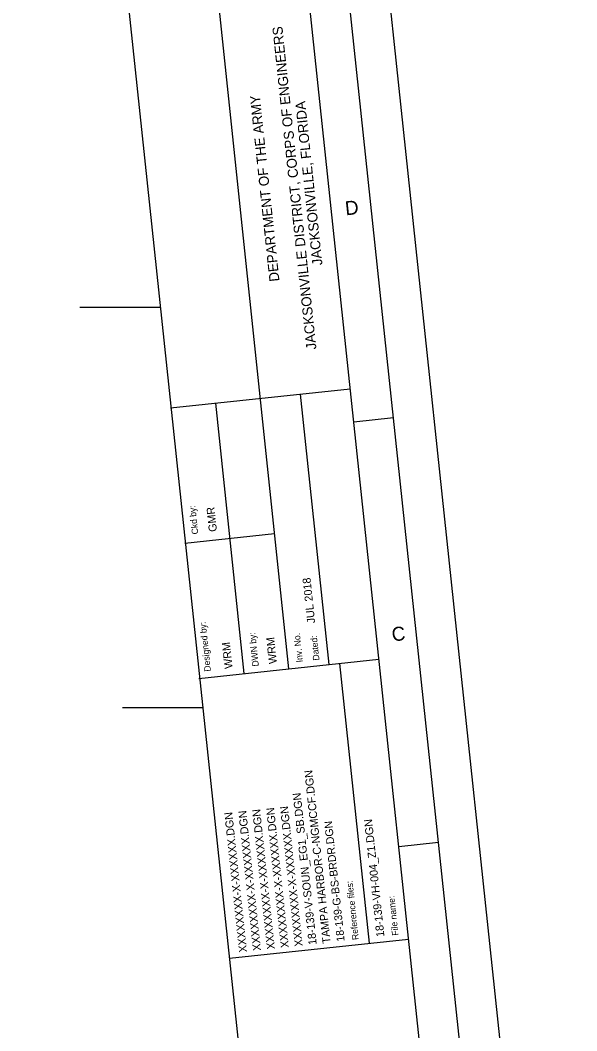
# Model space of a CAD drawing. Extents: x 341472 to 346206, y 1184213 to 1188058.
# Drawn here: x 345511 to 346206, y 1185596 to 1186858 of the extents above; entities that cross this region are included whole.
import ezdxf

# ---------------------------------------------------------------- set-up
doc = ezdxf.new("R2010")
doc.units = 0
for name, color, linetype in [('G-ANNO-NPLT', 7, 'Continuous'), ('G-ANNO-TEXT-DRWG', 7, 'Continuous'), ('G-ANNO-TEXT-PROJ', 7, 'Continuous'), ('G-ANNO-TEXT-TTLB', 7, 'Continuous'), ('G-ANNO-TTLB', 7, 'Continuous'), ('V-TOPO-COOR-STAT', 7, 'Continuous')]:
    doc.layers.add(name, color=color, linetype=linetype)

msp = doc.modelspace()

# ---------------------------------------------------------------- linework, layer by layer
at = {"layer": 'G-ANNO-NPLT'}
msp.add_lwpolyline([(341472, 1187593.7), (345847.5, 1188057.5), (346205.9, 1184676.5), (341830.4, 1184212.7)], close=True, dxfattribs=at)
at = {"layer": 'G-ANNO-TTLB'}
for p, q in [((345534.8, 1187923.8), (345872.1, 1184741.6)), ((345846.1, 1186048.3), (345756.1, 1186903.2)), ((345698.3, 1186374.2), (345922.8, 1186398)), ((345860.2, 1186391.4), (345896, 1186053.6)), ((345790.4, 1186042.5), (345754.9, 1186380.2)), ((345977, 1186361.6), (345927.2, 1186356.3)), ((345716.2, 1186205.3), (345828.3, 1186217.2)), ((345733.7, 1186036.4), (345958.6, 1186060.3)), ((345909.6, 1186055.1), (345946.6, 1185705.6)), ((346033.2, 1185831.3), (345983.4, 1185826)), ((345771.9, 1185687.1), (345995.7, 1185710.8))]:
    msp.add_line(p, q, dxfattribs=at)
for points in [[(341874.8, 1184267.7), (346150.9, 1184720.9), (345803, 1188002.5), (341527, 1187549.3)], [(345758.6, 1187947.5), (341656.6, 1187512.7), (341993.9, 1184330.6), (346095.9, 1184765.4)]]:
    msp.add_lwpolyline(points, close=True, dxfattribs=at)
at = {"layer": 'V-TOPO-COOR-STAT'}
for p, q in [((345585.2, 1186500), (345685.7, 1186500)), ((345638.2, 1186000), (345738.7, 1186000))]:
    msp.add_line(p, q, dxfattribs=at)

# ---------------------------------------------------------------- texts
at = {"layer": 'G-ANNO-TEXT-DRWG'}
for s, p in [('GMR', (345756.4, 1186220)), ('WRM', (345776, 1186049)), ('WRM', (345831.3, 1186055.1)), ('TAMPA HARBOR-C-NGMCCF.DGN', (345898.4, 1185705.9)), ('18-139-V-SOUN_EG1_SB.DGN', (345881, 1185704.1)), ('XXXXXXXX-X-XXXXXX.DGN', (345863.6, 1185702.2)), ('XXXXXXXX-X-XXXXXX.DGN', (345794, 1185694.8)), ('XXXXXXXX-X-XXXXXX.DGN', (345811.4, 1185696.7)), ('XXXXXXXX-X-XXXXXX.DGN', (345828.8, 1185698.5)), ('XXXXXXXX-X-XXXXXX.DGN', (345846.2, 1185700.4)), ('18-139-VH-004_Z1.DGN', (345965.6, 1185714.1))]:
    msp.add_text(s, height=10, rotation=96.0506, dxfattribs=at).set_placement(p)
at = {"layer": 'G-ANNO-TEXT-PROJ'}
for s, height, p in [('JUL 2018', 10, (345879.1, 1186105.7)), ('18-139-G-BS-BRDR.DGN', 9.8, (345915.9, 1185708.2))]:
    msp.add_text(s, height=height, rotation=96.0506, dxfattribs=at).set_placement(p)
at = {"layer": 'G-ANNO-TEXT-TTLB'}
for s, height, p in [('JACKSONVILLE DISTRICT, CORPS OF ENGINEERS', 12.5, (345880.7, 1186447.6)), ('DEPARTMENT OF THE ARMY', 12.5, (345834.5, 1186532.6)), ('JACKSONVILLE, FLORIDA', 12.5, (345888.2, 1186552.8)), ('Ckd by:', 8, (345733.1, 1186216.7)), ('Designed by:', 8, (345748.8, 1186045.3)), ('DWN by:', 8, (345808.7, 1186051.7)), ('Inv. No.', 8, (345863.7, 1186056.8)), ('Dated:', 8, (345884.4, 1186059.1)), ('Reference files:', 8, (345933.5, 1185710.1)), ('File name:', 8, (345983.2, 1185715.6))]:
    msp.add_text(s, height=height, rotation=96.0506, dxfattribs=at).set_placement(p)
at = {"layer": 'G-ANNO-TTLB'}
for s, p in [('D', (345917.3, 1186614.6)), ('C', (345975.6, 1186082.5))]:
    msp.add_text(s, height=17.5, rotation=6.0506, dxfattribs=at).set_placement(p)

doc.saveas('drawing.dxf')
